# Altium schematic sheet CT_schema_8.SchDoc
size 278 x 170 mm
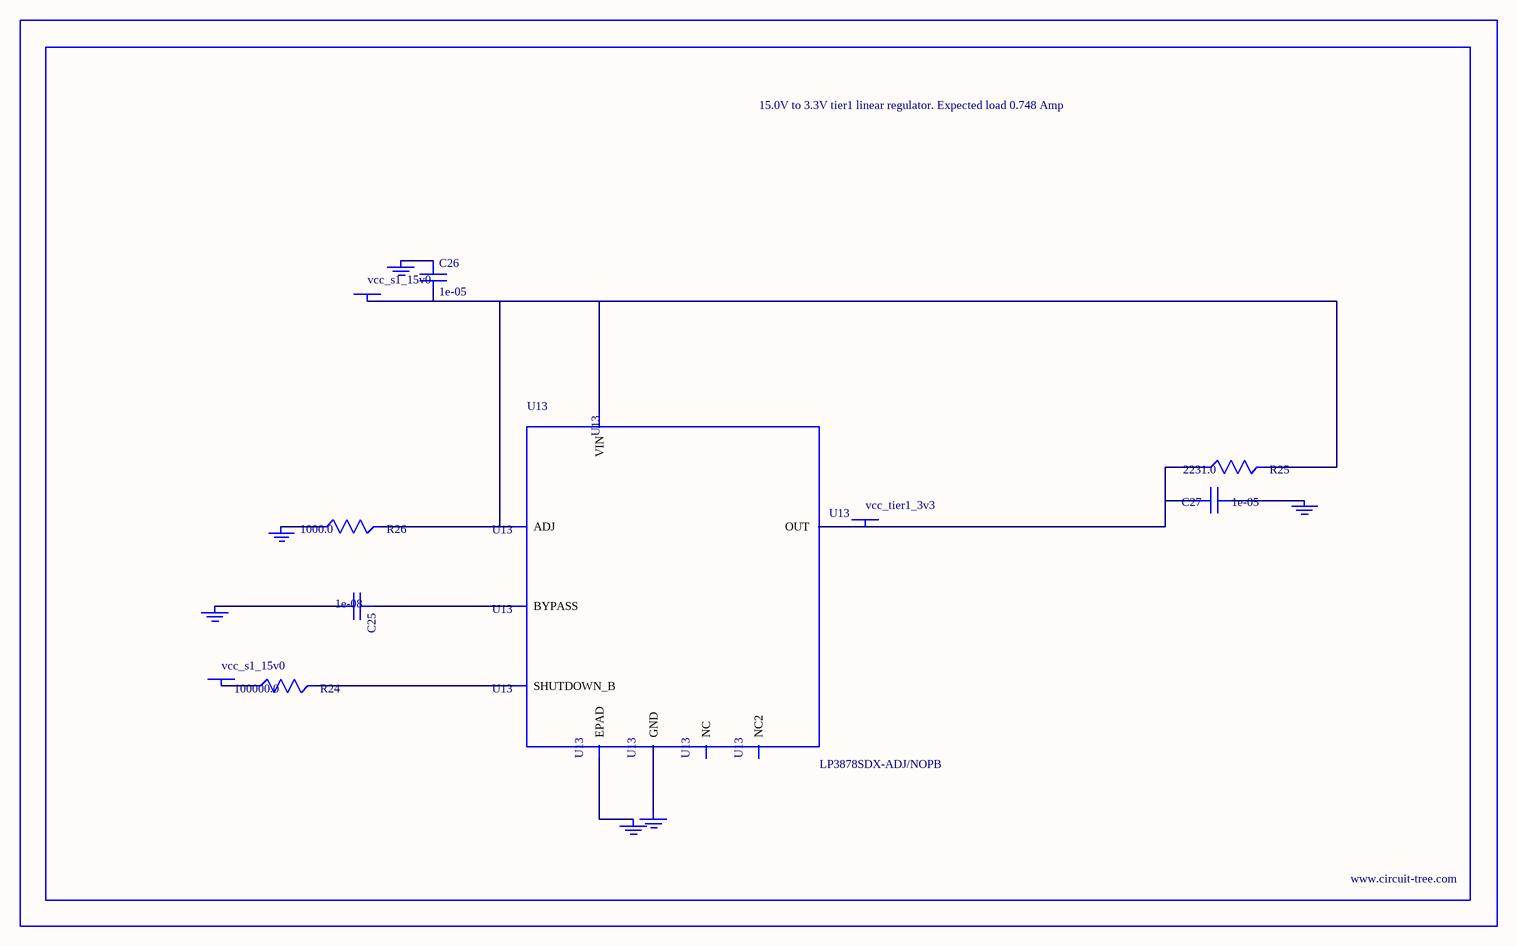
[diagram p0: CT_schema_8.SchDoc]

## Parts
BORDER7  (no value)
C25  1e-08  [C0402]
C26  1e-05  [C1210]
C27  1e-05  [C1210]
GND_INSTANCE_7_0  (no value)
GND_INSTANCE_7_1  (no value)
GND_INSTANCE_7_2  (no value)
GND_INSTANCE_7_3  (no value)
GND_INSTANCE_7_4  (no value)
GND_INSTANCE_7_5  (no value)
POWER_INSTANCE_7_0  vcc_s1_15v0
POWER_INSTANCE_7_1  vcc_s1_15v0
POWER_INSTANCE_7_2  vcc_tier1_3v3
R24  100000.0  [R0603]
R25  2231.0  [R0603]
R26  1000.0  [R0603]
U13  LP3878SDX-ADJ/NOPB  [WSON-8]

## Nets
NetC25_1: C25.1 U13.1(BYPASS)
NetC25_2: C25.2 GND_INSTANCE_7_0.0(GND)
NetC26_1: C26.1 GND_INSTANCE_7_1.0(GND)
NetC26_2: C26.2 POWER_INSTANCE_7_0.0(PWR) R25.2 R26.2 U13.4(VIN) U13.6(ADJ)
NetC27_1: C27.1 GND_INSTANCE_7_2.0(GND)
NetC27_2: C27.2 POWER_INSTANCE_7_2.0(PWR) R25.1 U13.5(OUT)
NetGND_INSTANCE_7_3_0: GND_INSTANCE_7_3.0(GND) R26.1
NetGND_INSTANCE_7_4_0: GND_INSTANCE_7_4.0(GND) U13.PAD(EPAD)
NetGND_INSTANCE_7_5_0: GND_INSTANCE_7_5.0(GND) U13.3(GND)
NetPOWER_INSTANCE_7_1_0: POWER_INSTANCE_7_1.0(PWR) R24.1
NetR24_2: R24.2 U13.8(SHUTDOWN_B)

Not connected (* = marked no-connect by the designer): U13 2(NC) 7(NC2)

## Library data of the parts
BORDER7 = BORDER_PAGE7
C25 = C0402C103K3RAC
C26 = C1210C106K5PACTU
C27 = GRM32DR61E106MA12L
GND_INSTANCE_7_0-GND_INSTANCE_7_5 = GND
POWER_INSTANCE_7_0-POWER_INSTANCE_7_2 = PWR
R24 = RC0603JR-07100KL
R25 = R25
R26 = RC0603JR-071KL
